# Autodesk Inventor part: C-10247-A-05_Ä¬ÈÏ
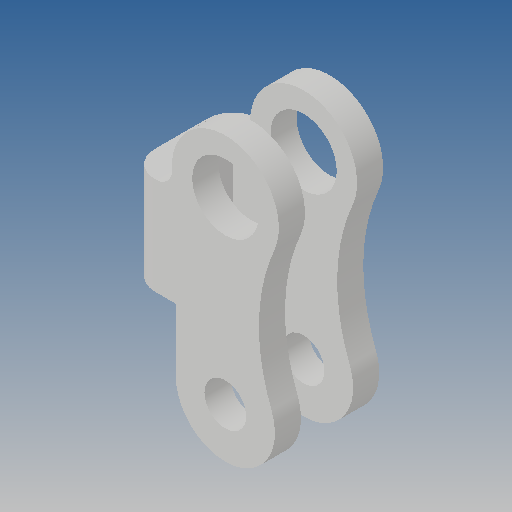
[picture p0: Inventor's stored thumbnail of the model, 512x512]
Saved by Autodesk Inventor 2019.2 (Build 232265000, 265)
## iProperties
Created: 2010-06
Part Number: C-10247-A-05_Ä¬ÈÏ
Material: Ogólny
Document SubType Name: Modeling
Designer: CADENGINEERING4
Density: 1 g/cm^3
Appearance: Domyślna
Author: CADENGINEERING4
Revision Number: ÈÎºÎ
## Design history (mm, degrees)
feature "NONE"
node "Bryła1"
